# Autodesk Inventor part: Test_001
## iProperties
Created: 2009-08
Part Number: Test_001
Document SubType Name: Modeling
Designer: 10172392
Density: 1 g/cm^3
Author: 10172392
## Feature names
1. Extrusion1
2. Extrusion2
